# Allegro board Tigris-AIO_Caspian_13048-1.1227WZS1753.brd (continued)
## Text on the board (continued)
User.45: AGND | GND | This gerber is just for you reference to find the differential traces in layer BOTTOM | This gerber is just for you reference to find the differential traces in layer L3 | This gerber is just for you reference to find the differential traces in layer L4 | This gerber is just for you reference to find the differential traces in layer TOP | Note:Refer to DRILL layer for ELLIPSE drill direction | FIGURE | SIZE | 10.0 | 12.0 | 16.0 | 20.0 | 28.0 | 30.0 | 32.0 | 35.0 | 36.0 | 37.0 | 39.0 | 40.0 | 41.0 | 45.0 | 47.0 | 54.0 | 62.0 | 68.0 | 91.0 | 109.0 | 126.0 | 157.0 | 42.0 | 44.0 | 50.0 | 63.0 | 65.0 | 86.0 | 138.0 | 150.0 | 177.0 | 56.0x24.0 | 60.0x24.0 | 60.0x28.0 | 91.0x32.0 | 148.0x24.0 | 150.0x32.0 | DRILL CHART: TOP to BOTTOM | ALL UNITS ARE IN MILS | PLATED | NON-PLATED | QTY | 1809 | 2476 | 1166 | 40 | 18 | 14 | 5 | 28 | 24 | 16 | 44 | 4 | 2 | 8 | 3 | 1 | 7 | This gerber is just for your reference to find the DP impedance traces in layer L1. | This gerber is just for your reference to find the DP impedance traces in layer L3. | This gerber is just for your reference to find the DP impedance traces in layer L4. | This gerber is just for your reference to find the DP impedance traces in layer L6. | This gerber is just for your reference to find the SE impedance traces in layer L1. | This gerber is just for your reference to find the SE impedance traces in layer L3. | This gerber is just for your reference to find the SE impedance traces in layer L4. | This gerber is just for your reference to find the SE impedance traces in layer L6. | DP IMPEDANCE TABLE: L1 | DP IMPEDANCE TABLE: L3 | DP IMPEDANCE TABLE: L4 | DP IMPEDANCE TABLE: L6 | SE IMPEDANCE TABLE: L1 | SE IMPEDANCE TABLE: L3 | SE IMPEDANCE TABLE: L4 | SE IMPEDANCE TABLE: L6 | * - Denotes that WIDTH | is NOT used in this layer | inside board outline. | Model | Tigris AIO MB | PCB_NO | 13048 | VER. | Layer | DRILL | L1 | L2GND | L3 | TMASK | TPLACE | TSILK | TSMD | Designer | Elyn | Date | 12/27/2013 | IMP(Ohm) | 27.4 | 33.0 | 34.0 | 70.0 | 72.0 | 37.5 | 75.0 | 80.0 | 85.0 | 90.0 | 48.0 | 93.0 | 52.0 | 95.0 | 100.0 | 55.0 | 110.0 | WIDTH(mils) | *16.0 | *9.0 | *8.5 | 11.5 | 8.5 | *10.5 | 10.5 | 8.0 | *7.0 | *9.5 | 7.0 | 6.5 | 9.0 | *5.5 | 5.5 | 7.5 | 5.0 | *4.5 | 4.0 | *3.5 | *nil | *8.0/6.0 | *9.0/5.0 | *6.5/4.0 | 7.5/4.0 | *7.0/6.0 | *7.0/5.0 | *7.0/8.0 | *6.0/6.0 | 5.0/5.0 | 6.0/6.0 | *5.0/8.0 | 5.0/5.5 | 4.0/4.5 | 4.0/5.0 | 4.0/6.0 | *4.0/8.0 | *5.0/9.0 | *3.5/5.5 | *4.0/5.5 | *4.0/10.0 | *4.0/6.5 | 4.0/10.0 | *3.5/6.0 | *4.0/9.0 | *3.5/10.0 | *3.5/13.0 | 3.5/10.0 | TYPE | SE | DP | BMASK | BPLACE | BSILK | BSMD | L4 | L5GND | L6
